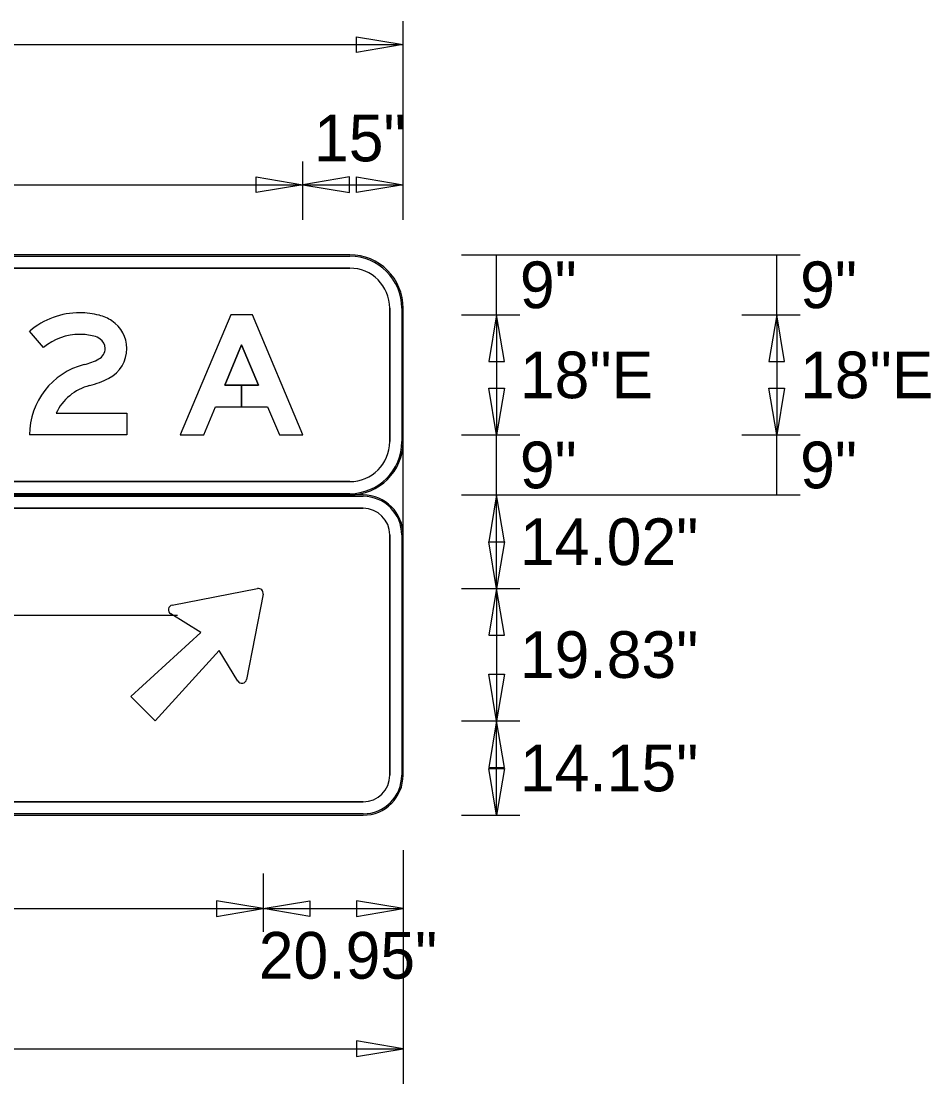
# Model space of a CAD drawing. Extents: x 2149934 to 2150188, y 145114 to 145238.
# Drawn here: x 2150103.01 to 2150114.37, y 145195.09 to 145208.36 of the extents above; entities that cross this region are included whole.
import ezdxf

# ---------------------------------------------------------------- set-up
doc = ezdxf.new("R2010")
doc.units = 0
for name, color, linetype in [('GSBWFILL', 7, 'Continuous'), ('GSCOLORFILL', 7, 'Continuous'), ('GSDIMS', 7, 'Continuous'), ('GSOUTLINE', 7, 'Continuous'), ('NON-PLOT', 7, 'Continuous')]:
    doc.layers.add(name, color=color, linetype=linetype)

msp = doc.modelspace()

# ---------------------------------------------------------------- linework, layer by layer
at = {"layer": 'GSBWFILL'}
for p, q in [((2150107.112, 145205.445), (2150095.445, 145205.445)), ((2150095.445, 145205.278), (2150107.112, 145205.278)), ((2150107.612, 145204.778), (2150107.612, 145203.111)), ((2150107.779, 145203.111), (2150107.779, 145204.778)), ((2150107.112, 145202.611), (2150095.447, 145202.611)), ((2150107.279, 145202.445), (2150088.779, 145202.445)), ((2150095.447, 145202.445), (2150107.112, 145202.445)), ((2150088.779, 145202.278), (2150107.279, 145202.278)), ((2150107.612, 145201.945), (2150107.612, 145198.945)), ((2150107.779, 145198.945), (2150107.779, 145201.945)), ((2150107.279, 145198.611), (2150088.78, 145198.611)), ((2150088.78, 145198.445), (2150107.279, 145198.445))]:
    msp.add_line(p, q, dxfattribs=at)
msp.add_lwpolyline([(2150105.972, 145203.817), (2150105.761, 145203.817), (2150105.761, 145203.547), (2150106.085, 145203.547), (2150106.233, 145203.195), (2150106.526, 145203.195), (2150105.896, 145204.695), (2150105.626, 145204.695), (2150104.996, 145203.195), (2150105.289, 145203.195), (2150105.437, 145203.547), (2150105.761, 145203.547), (2150105.761, 145203.817), (2150105.55, 145203.817), (2150105.761, 145204.319)], close=True, dxfattribs=at)
for points in [[(2150103.289, 145204.285), (2150103.114, 145204.491)], [(2150103.445, 145203.465), (2150104.329, 145203.465), (2150104.329, 145203.195), (2150103.114, 145203.195)], [(2150104.896, 145201.069), (2150105.96, 145201.276)], [(2150106.03, 145201.205), (2150105.824, 145200.141)], [(2150105.714, 145200.121), (2150105.482, 145200.5), (2150104.68, 145199.624), (2150104.379, 145199.926), (2150105.254, 145200.728), (2150104.876, 145200.959)]]:
    msp.add_lwpolyline(points, dxfattribs=at)
for centre, radius, start, end in [((2150107.112, 145204.778), 0.667, 0, 90), ((2150107.112, 145204.778), 0.5, 0, 90), ((2150107.112, 145203.111), 0.667, 270, 0), ((2150107.112, 145203.111), 0.5, 270, 0), ((2150107.279, 145201.945), 0.5, 0, 90), ((2150107.279, 145201.945), 0.333, 0, 90), ((2150105.971, 145201.217), 0.06, 349.0223, 100.9777), ((2150104.907, 145201.01), 0.06, 100.9777, 238.5155), ((2150105.765, 145200.153), 0.06, 211.4845, 349.0223), ((2150107.279, 145198.945), 0.5, 270, 0), ((2150107.279, 145198.945), 0.333, 270, 0)]:
    msp.add_arc(centre, radius, start, end, dxfattribs=at)
for centre, major_axis, start_param, end_param in [((2150103.741, 145203.753), (0, 0.968), 0, 0.70376), ((2150103.741, 145203.773), (0, 0.948), 6.02311, 6.283185), ((2150103.843, 145204.158), (0, 0.55), 5.706931, 6.02311), ((2150103.919, 145204.275), (0, 0.41), 4.712389, 5.706931), ((2150103.741, 145203.753), (0, 0.698), 0, 0.70376), ((2150103.741, 145203.773), (0, 0.678), 6.02311, 6.283185), ((2150103.843, 145204.158), (0, 0.28), 5.706931, 6.02311), ((2150103.919, 145204.275), (0, 0.14), 4.712389, 5.706931), ((2150103.91, 145204.275), (0, 0.149), 3.626327, 4.712389), ((2150103.91, 145204.275), (0, 0.419), 3.626327, 4.712389), ((2150104.02, 145203.195), (0, 0.906), 0.25053, 1.570796), ((2150103.586, 145204.891), (0, 0.845), 3.392123, 3.626327), ((2150103.586, 145204.891), (0, 1.115), 3.392123, 3.626327), ((2150104.02, 145203.195), (0, 0.636), 0.25053, 1.132058)]:
    msp.add_ellipse(centre, major_axis=major_axis, ratio=0.999997, start_param=start_param, end_param=end_param, dxfattribs=at)
at = {"layer": 'GSCOLORFILL'}
for p, q in [((2150107.112, 145205.445), (2150095.445, 145205.445)), ((2150107.112, 145205.445), (2150095.445, 145205.445)), ((2150107.112, 145205.445), (2150095.445, 145205.445)), ((2150095.445, 145205.428), (2150107.112, 145205.428)), ((2150095.445, 145205.278), (2150107.112, 145205.278)), ((2150107.612, 145204.778), (2150107.612, 145203.111)), ((2150107.762, 145204.778), (2150107.762, 145203.111)), ((2150107.779, 145203.111), (2150107.779, 145204.778)), ((2150107.779, 145203.111), (2150107.779, 145204.778)), ((2150107.779, 145203.111), (2150107.779, 145204.778)), ((2150107.112, 145202.611), (2150095.447, 145202.611)), ((2150107.279, 145202.445), (2150088.779, 145202.445)), ((2150107.279, 145202.445), (2150088.779, 145202.445)), ((2150107.279, 145202.445), (2150088.779, 145202.445)), ((2150088.779, 145202.428), (2150107.279, 145202.428)), ((2150107.112, 145202.461), (2150095.445, 145202.461)), ((2150095.445, 145202.445), (2150107.112, 145202.445)), ((2150095.445, 145202.445), (2150107.112, 145202.445)), ((2150095.447, 145202.445), (2150107.112, 145202.445)), ((2150088.779, 145202.278), (2150107.279, 145202.278)), ((2150107.612, 145201.945), (2150107.612, 145198.945)), ((2150107.762, 145201.945), (2150107.762, 145198.945)), ((2150107.779, 145198.945), (2150107.779, 145201.945)), ((2150107.779, 145198.945), (2150107.779, 145201.945)), ((2150107.779, 145198.945), (2150107.779, 145201.945)), ((2150107.279, 145198.611), (2150088.78, 145198.611)), ((2150107.279, 145198.461), (2150088.779, 145198.461)), ((2150088.779, 145198.445), (2150107.279, 145198.445)), ((2150088.779, 145198.445), (2150107.279, 145198.445)), ((2150088.78, 145198.445), (2150107.279, 145198.445))]:
    msp.add_line(p, q, dxfattribs=at)
msp.add_lwpolyline([(2150105.972, 145203.817), (2150105.761, 145203.817), (2150105.761, 145203.547), (2150106.085, 145203.547), (2150106.233, 145203.195), (2150106.526, 145203.195), (2150105.896, 145204.695), (2150105.626, 145204.695), (2150104.996, 145203.195), (2150105.289, 145203.195), (2150105.437, 145203.547), (2150105.761, 145203.547), (2150105.761, 145203.817), (2150105.55, 145203.817), (2150105.761, 145204.319)], close=True, dxfattribs=at)
for points in [[(2150103.289, 145204.285), (2150103.114, 145204.491)], [(2150103.445, 145203.465), (2150104.329, 145203.465), (2150104.329, 145203.195), (2150103.114, 145203.195)], [(2150104.896, 145201.069), (2150105.96, 145201.276)], [(2150106.03, 145201.205), (2150105.824, 145200.141)], [(2150105.714, 145200.121), (2150105.482, 145200.5), (2150104.68, 145199.624), (2150104.379, 145199.926), (2150105.254, 145200.728), (2150104.876, 145200.959)]]:
    msp.add_lwpolyline(points, dxfattribs=at)
for centre, radius, start, end in [((2150107.112, 145204.778), 0.667, 0, 90), ((2150107.112, 145204.778), 0.667, 0, 90), ((2150107.112, 145204.778), 0.667, 0, 90), ((2150107.112, 145204.778), 0.65, 0, 90), ((2150107.112, 145204.778), 0.5, 0, 90), ((2150107.112, 145203.111), 0.667, 270, 0), ((2150107.112, 145203.111), 0.667, 270, 0), ((2150107.112, 145203.111), 0.5, 270, 0), ((2150107.112, 145203.111), 0.667, 270, 0), ((2150107.112, 145203.111), 0.65, 270, 0), ((2150107.279, 145201.945), 0.5, 0, 90), ((2150107.279, 145201.945), 0.5, 0, 90), ((2150107.279, 145201.945), 0.5, 0, 90), ((2150107.279, 145201.945), 0.483, 0, 90), ((2150107.279, 145201.945), 0.333, 0, 90), ((2150105.971, 145201.217), 0.06, 349.0223, 100.9777), ((2150104.907, 145201.01), 0.06, 100.9777, 238.5155), ((2150105.765, 145200.153), 0.06, 211.4845, 349.0223), ((2150107.279, 145198.945), 0.5, 270, 0), ((2150107.279, 145198.945), 0.5, 270, 0), ((2150107.279, 145198.945), 0.333, 270, 0), ((2150107.279, 145198.945), 0.5, 270, 0), ((2150107.279, 145198.945), 0.483, 270, 0)]:
    msp.add_arc(centre, radius, start, end, dxfattribs=at)
for centre, major_axis, start_param, end_param in [((2150103.741, 145203.753), (0, 0.968), 0, 0.70376), ((2150103.741, 145203.773), (0, 0.948), 6.02311, 6.283185), ((2150103.843, 145204.158), (0, 0.55), 5.706931, 6.02311), ((2150103.919, 145204.275), (0, 0.41), 4.712389, 5.706931), ((2150103.741, 145203.753), (0, 0.698), 0, 0.70376), ((2150103.741, 145203.773), (0, 0.678), 6.02311, 6.283185), ((2150103.843, 145204.158), (0, 0.28), 5.706931, 6.02311), ((2150103.919, 145204.275), (0, 0.14), 4.712389, 5.706931), ((2150103.91, 145204.275), (0, 0.149), 3.626327, 4.712389), ((2150103.91, 145204.275), (0, 0.419), 3.626327, 4.712389), ((2150104.02, 145203.195), (0, 0.906), 0.25053, 1.570796), ((2150103.586, 145204.891), (0, 0.845), 3.392123, 3.626327), ((2150103.586, 145204.891), (0, 1.115), 3.392123, 3.626327), ((2150104.02, 145203.195), (0, 0.636), 0.25053, 1.132058)]:
    msp.add_ellipse(centre, major_axis=major_axis, ratio=0.999997, start_param=start_param, end_param=end_param, dxfattribs=at)
at = {"layer": 'GSDIMS'}
for p, q in [((2150107.779, 145207.633), (2150107.779, 145208.362)), ((2150094.778, 145208.07), (2150107.779, 145208.07)), ((2150107.779, 145205.883), (2150107.779, 145207.633)), ((2150106.526, 145205.883), (2150106.526, 145206.612)), ((2150106.526, 145205.883), (2150106.526, 145206.612)), ((2150107.779, 145205.883), (2150107.779, 145206.612)), ((2150096.029, 145206.32), (2150106.526, 145206.32)), ((2150106.526, 145206.32), (2150107.779, 145206.32)), ((2150108.508, 145205.445), (2150109.237, 145205.445)), ((2150108.508, 145205.445), (2150112.008, 145205.445)), ((2150108.945, 145204.695), (2150108.945, 145205.445)), ((2150112.008, 145205.445), (2150112.737, 145205.445)), ((2150112.445, 145204.695), (2150112.445, 145205.445)), ((2150108.508, 145204.695), (2150109.237, 145204.695)), ((2150108.508, 145204.695), (2150109.237, 145204.695)), ((2150108.945, 145204.695), (2150108.945, 145203.195)), ((2150112.008, 145204.695), (2150112.737, 145204.695)), ((2150112.008, 145204.695), (2150112.737, 145204.695)), ((2150112.445, 145204.695), (2150112.445, 145203.195)), ((2150108.508, 145203.195), (2150109.237, 145203.195)), ((2150108.508, 145203.195), (2150109.237, 145203.195)), ((2150108.945, 145202.445), (2150108.945, 145203.195)), ((2150112.008, 145203.195), (2150112.737, 145203.195)), ((2150112.008, 145203.195), (2150112.737, 145203.195)), ((2150112.445, 145202.445), (2150112.445, 145203.195)), ((2150108.508, 145202.445), (2150109.237, 145202.445)), ((2150108.508, 145202.445), (2150108.508, 145202.445)), ((2150108.508, 145202.445), (2150109.237, 145202.445)), ((2150108.508, 145202.445), (2150112.008, 145202.445)), ((2150108.945, 145201.277), (2150108.945, 145202.445)), ((2150112.008, 145202.445), (2150112.737, 145202.445)), ((2150108.508, 145201.277), (2150109.237, 145201.277)), ((2150108.508, 145201.277), (2150109.237, 145201.277)), ((2150108.945, 145201.277), (2150108.945, 145199.624)), ((2150108.508, 145199.624), (2150109.237, 145199.624)), ((2150108.508, 145199.624), (2150109.237, 145199.624)), ((2150108.945, 145198.445), (2150108.945, 145199.624)), ((2150108.508, 145198.445), (2150109.237, 145198.445)), ((2150108.508, 145198.445), (2150108.508, 145198.445)), ((2150107.779, 145198.007), (2150107.779, 145195.091)), ((2150106.031, 145197.716), (2150106.031, 145196.986)), ((2150106.031, 145197.716), (2150106.031, 145196.986)), ((2150107.779, 145197.716), (2150107.779, 145196.986)), ((2150090.026, 145197.278), (2150106.031, 145197.278)), ((2150106.031, 145197.278), (2150107.779, 145197.278)), ((2150107.779, 145195.966), (2150107.779, 145195.236)), ((2150088.279, 145195.528), (2150107.779, 145195.528))]:
    msp.add_line(p, q, dxfattribs=at)
for points in [[(2150107.779, 145208.07), (2150107.195, 145207.973), (2150107.195, 145208.167)], [(2150106.526, 145206.32), (2150105.943, 145206.223), (2150105.943, 145206.417)], [(2150106.526, 145206.32), (2150107.109, 145206.223), (2150107.109, 145206.417)], [(2150107.779, 145206.32), (2150107.195, 145206.223), (2150107.195, 145206.417)], [(2150108.945, 145204.695), (2150108.848, 145204.111), (2150109.043, 145204.111)], [(2150112.445, 145204.695), (2150112.348, 145204.111), (2150112.543, 145204.111)], [(2150108.945, 145203.195), (2150108.848, 145203.778), (2150109.043, 145203.778)], [(2150112.445, 145203.195), (2150112.348, 145203.778), (2150112.543, 145203.778)], [(2150108.945, 145202.445), (2150108.848, 145201.861), (2150109.043, 145201.861)], [(2150108.945, 145201.277), (2150108.848, 145201.86), (2150109.043, 145201.86)], [(2150108.945, 145201.277), (2150108.848, 145200.693), (2150109.043, 145200.693)], [(2150108.945, 145199.624), (2150108.848, 145200.207), (2150109.043, 145200.207)], [(2150108.945, 145199.624), (2150108.848, 145199.041), (2150109.043, 145199.041)], [(2150108.945, 145198.445), (2150108.848, 145199.028), (2150109.043, 145199.028)], [(2150106.031, 145197.278), (2150105.448, 145197.375), (2150105.448, 145197.181)], [(2150106.031, 145197.278), (2150106.615, 145197.375), (2150106.615, 145197.181)], [(2150107.779, 145197.278), (2150107.195, 145197.375), (2150107.195, 145197.181)], [(2150107.779, 145195.528), (2150107.195, 145195.625), (2150107.195, 145195.431)]]:
    msp.add_lwpolyline(points, close=True, dxfattribs=at)
at = {"layer": 'GSOUTLINE'}
for p, q in [((2150107.112, 145205.445), (2150095.445, 145205.445)), ((2150107.112, 145205.278), (2150095.445, 145205.278)), ((2150107.612, 145203.111), (2150107.612, 145204.778)), ((2150107.779, 145203.111), (2150107.779, 145204.778)), ((2150095.445, 145202.611), (2150107.112, 145202.611)), ((2150107.279, 145202.445), (2150088.779, 145202.445)), ((2150095.445, 145202.445), (2150107.112, 145202.445)), ((2150107.279, 145202.278), (2150088.779, 145202.278)), ((2150107.612, 145198.945), (2150107.612, 145201.945)), ((2150107.779, 145198.945), (2150107.779, 145201.945)), ((2150088.779, 145198.611), (2150107.279, 145198.611)), ((2150088.779, 145198.445), (2150107.279, 145198.445))]:
    msp.add_line(p, q, dxfattribs=at)
for points in [[(2150105.437, 145203.547), (2150106.085, 145203.547), (2150106.233, 145203.195), (2150106.526, 145203.195), (2150105.896, 145204.695), (2150105.626, 145204.695), (2150104.996, 145203.195), (2150105.289, 145203.195)], [(2150105.972, 145203.817), (2150105.761, 145204.319), (2150105.55, 145203.817)]]:
    msp.add_lwpolyline(points, close=True, dxfattribs=at)
for points in [[(2150103.289, 145204.285), (2150103.114, 145204.491)], [(2150103.445, 145203.465), (2150104.329, 145203.465), (2150104.329, 145203.195), (2150103.114, 145203.195)], [(2150104.896, 145201.069), (2150105.96, 145201.276)], [(2150106.03, 145201.205), (2150105.824, 145200.141)], [(2150105.714, 145200.121), (2150105.482, 145200.5), (2150104.68, 145199.624), (2150104.379, 145199.926), (2150105.254, 145200.728), (2150104.876, 145200.959)]]:
    msp.add_lwpolyline(points, dxfattribs=at)
for centre, radius, start, end in [((2150107.112, 145204.778), 0.667, 0, 90), ((2150107.112, 145204.778), 0.5, 0, 90), ((2150107.112, 145203.111), 0.667, 270, 0), ((2150107.112, 145203.111), 0.5, 270, 0), ((2150107.279, 145201.945), 0.5, 0, 90), ((2150107.279, 145201.945), 0.333, 0, 90), ((2150105.971, 145201.217), 0.06, 349.0223, 100.9777), ((2150104.907, 145201.01), 0.06, 100.9777, 238.5155), ((2150105.765, 145200.153), 0.06, 211.4845, 349.0223), ((2150107.279, 145198.945), 0.5, 270, 0), ((2150107.279, 145198.945), 0.333, 270, 0)]:
    msp.add_arc(centre, radius, start, end, dxfattribs=at)
for centre, major_axis, start_param, end_param in [((2150103.741, 145203.753), (0, 0.968), 0, 0.70376), ((2150103.741, 145203.773), (0, 0.948), 6.02311, 6.283185), ((2150103.843, 145204.158), (0, 0.55), 5.706931, 6.02311), ((2150103.919, 145204.275), (0, 0.41), 4.712389, 5.706931), ((2150103.741, 145203.753), (0, 0.698), 0, 0.70376), ((2150103.741, 145203.773), (0, 0.678), 6.02311, 6.283185), ((2150103.843, 145204.158), (0, 0.28), 5.706931, 6.02311), ((2150103.919, 145204.275), (0, 0.14), 4.712389, 5.706931), ((2150103.91, 145204.275), (0, 0.149), 3.626327, 4.712389), ((2150103.91, 145204.275), (0, 0.419), 3.626327, 4.712389), ((2150104.02, 145203.195), (0, 0.906), 0.25053, 1.570796), ((2150103.586, 145204.891), (0, 0.845), 3.392123, 3.626327), ((2150103.586, 145204.891), (0, 1.115), 3.392123, 3.626327), ((2150104.02, 145203.195), (0, 0.636), 0.25053, 1.132058)]:
    msp.add_ellipse(centre, major_axis=major_axis, ratio=0.999997, start_param=start_param, end_param=end_param, dxfattribs=at)
at = {"layer": 'NON-PLOT'}
for p, q in [((2150107.779, 145201.945), (2150107.779, 145203.111)), ((2150098.927, 145200.942), (2150104.959, 145200.942))]:
    msp.add_line(p, q, dxfattribs=at)

# ---------------------------------------------------------------- texts
at = {"layer": 'GSDIMS'}
for s, p in [('15"', (2150106.666, 145206.612)), ('9"', (2150109.237, 145204.778)), ('9"', (2150112.737, 145204.778)), ('18"E', (2150109.237, 145203.653)), ('18"E', (2150112.737, 145203.653)), ('9"', (2150109.237, 145202.528)), ('9"', (2150112.737, 145202.528)), ('14.02"', (2150109.237, 145201.569)), ('19.83"', (2150109.237, 145200.159)), ('14.15"', (2150109.237, 145198.743)), ('20.95"', (2150105.976, 145196.403))]:
    msp.add_text(s, height=0.5833, dxfattribs=at).set_placement(p)

doc.saveas('drawing.dxf')
